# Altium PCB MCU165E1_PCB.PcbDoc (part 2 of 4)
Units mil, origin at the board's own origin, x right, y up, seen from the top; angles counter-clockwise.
Board outline 2658.83 x 2179.35 mil, 6 copper layers (Top Signal Layer, GND1, Mid Layer, PWR, GND2, Bottom Signal Layer), stack 60.4 mil thick; 226 components, 197 nets, 947 pads, 562 vias.
Unrouted connection lines stored in the file: 81.
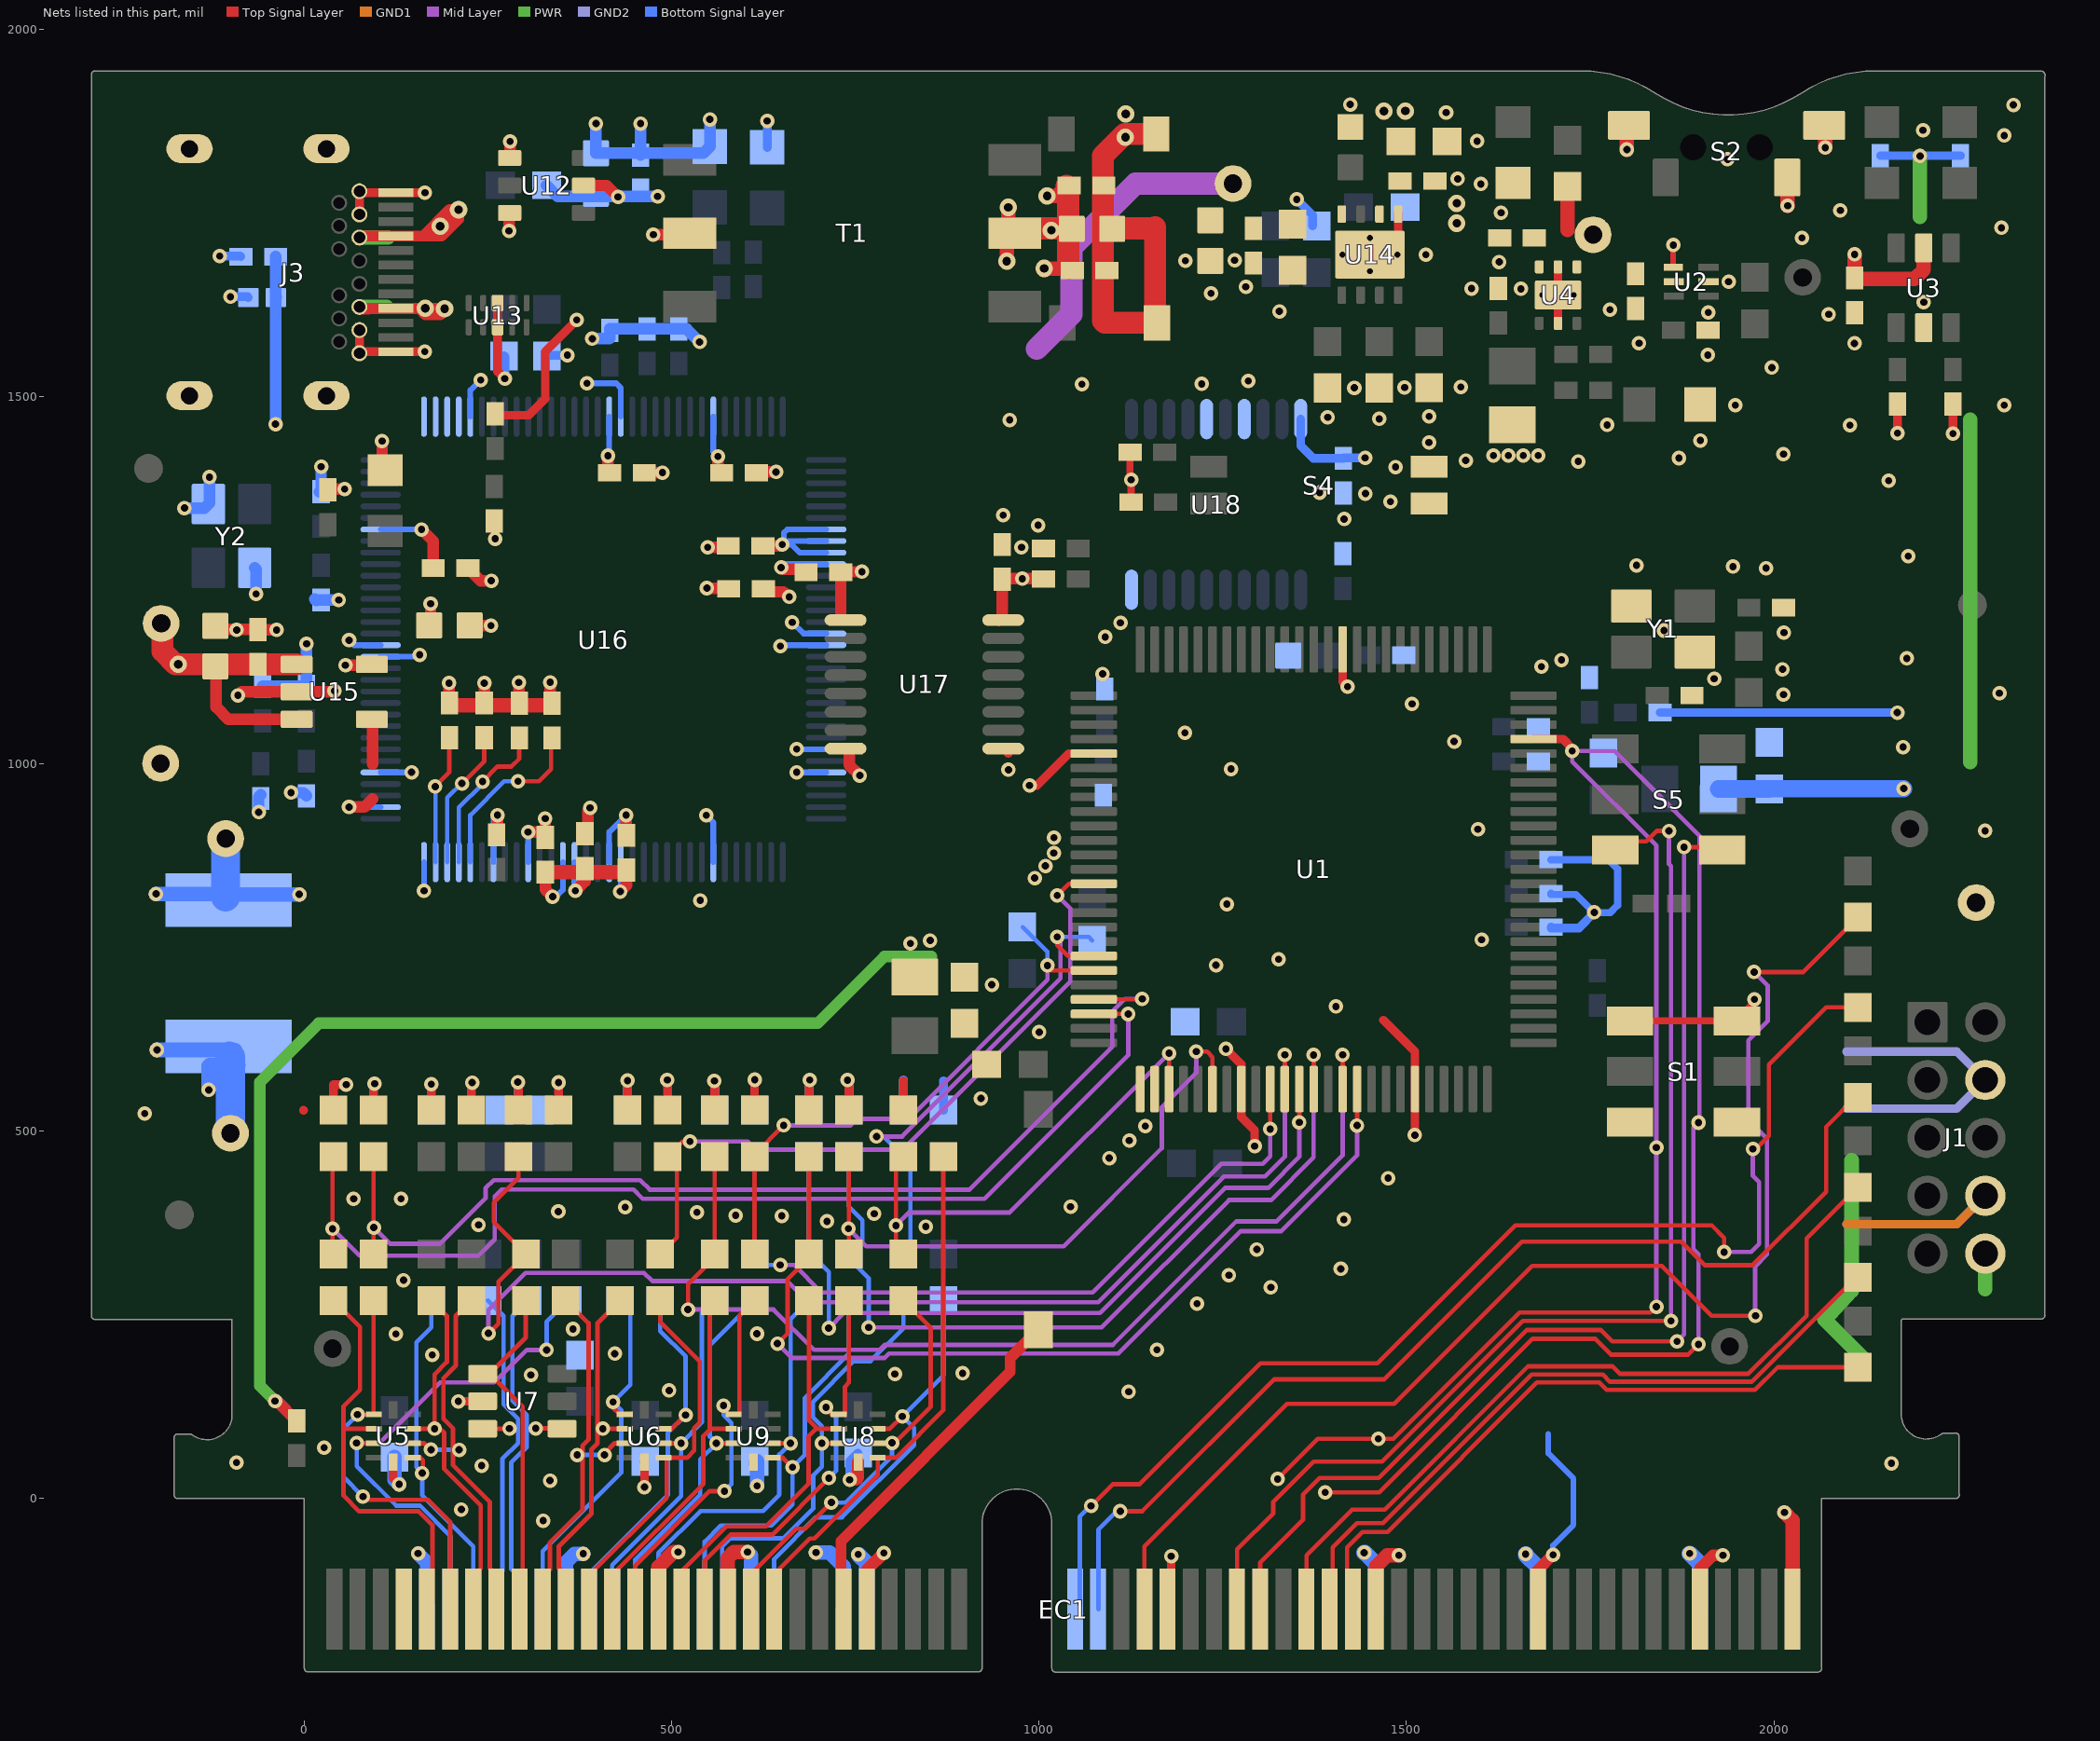
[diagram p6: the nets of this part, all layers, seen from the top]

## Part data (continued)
R13 R18: library part CMP-0026890-5, "RES, 2.2 k, 5%, 0.063 W, AEC-Q200 Grade 0, 0402", Manufacturer=Vishay-Dale, Power_W=63mW, Supplier Part Number 1=541-2.2KJCT-ND, TempCo="200 ppm/C", Tolerance_%=5%, Value2=0.063W, Value_Code=2k20, ValueDisplayed=2.2k
R16 R17: library part CMP-0026992-3, "RES, 0, 5%, 0.1 W, AEC-Q200 Grade 0, 0402", Manufacturer=Panasonic, Power_W=100mW, Supplier Part Number 1=P0.0JCT-ND, TempCo="600 ppm/C", Tolerance_%=5%, Value2=0.1W, Value_Code=0000, ValueDisplayed=0
R19 R20: library part CMP-0026979-3, "RES, 820, 5%, 0.063 W, AEC-Q200 Grade 0, 0402", Manufacturer=Vishay-Dale, Power_W=63mW, Supplier Part Number 1=541-820JCT-ND, TempCo="200 ppm/C", Tolerance_%=5%, Value2=0.063W, Value_Code=820R, ValueDisplayed=820
R21 R22: library part CMP-0026863-2, "RES, 1.5 M, 5%, 0.063 W, AEC-Q200 Grade 0, 0402", Manufacturer=Vishay-Dale, Power_W=63mW, Supplier Part Number 1=541-1.5MJCT-ND, TempCo="200 ppm/C", Tolerance_%=5%, Value2=0.063W, Value_Code=1M50, ValueDisplayed=1.5M
R23 R63 R67 R74: library part CMP-0025874-4, "RES, 0, 5%, 0.1 W, AEC-Q200 Grade 0, 0603", Manufacturer=Panasonic, Power_W=100mW, Supplier Part Number 1=P0.0GCT-ND, TempCo="600 ppm/C", Tolerance_%=5%, Value2=0.1W, Value_Code=0000, ValueDisplayed=0
R24: library part CMP-0020442-3, "RES, 0, 5%, 0.125 W, AEC-Q200 Grade 0, 0805", Manufacturer=Vishay-Dale, Power_W=125mW, Supplier Part Number 1=541-0.0ACT-ND, TempCo="200 ppm/C", Tolerance_%=5%, Value2=0.125W, Value_Code=0000, ValueDisplayed=0
R25: library part CMP-0026944-3, "RES, 510, 5%, 0.063 W, AEC-Q200 Grade 0, 0402", Manufacturer=Vishay-Dale, Power_W=63mW, Supplier Part Number 1=541-510JCT-ND, TempCo="200 ppm/C", Tolerance_%=5%, Value2=0.063W, Value_Code=510R, ValueDisplayed=510
R62: library part CMP-0026100-2, "RES, 1.00 M, 1%, 0.063 W, AEC-Q200 Grade 0, 0402", Manufacturer=Vishay-Dale, Power_W=63mW, Supplier Part Number 1=541-1.00MLCT-ND, TempCo="100 ppm/C", Tolerance_%=1%, Value2=0.063W, Value_Code=1M00, ValueDisplayed=1.00M
R64 R65: library part CMP-0025932-5, "RES, 5.1 k, 5%, 0.1 W, 0603", Manufacturer=Yageo, Power_W=100mW, Supplier Part Number 1=311-5.1KGRCT-ND, TempCo="100 ppm/C", Tolerance_%=5%, Value2=0.1W, Value_Code=5k10, ValueDisplayed=5.1k
R66: library part CMP-0025769-4, "RES, 2.2 k, 5%, 0.1 W, AEC-Q200 Grade 0, 0603", Manufacturer=Vishay-Dale, Power_W=100mW, Supplier Part Number 1=541-2.2KGCT-ND, TempCo="200 ppm/C", Tolerance_%=5%, Value2=0.1W, Value_Code=2k20, ValueDisplayed=2.2k
R68 R69: library part CMP-0025701-4, "RES, 10 k, 5%, 0.1 W, AEC-Q200 Grade 0, 0603", Manufacturer=Vishay-Dale, Power_W=100mW, Supplier Part Number 1=541-10KGCT-ND, TempCo="200 ppm/C", Tolerance_%=5%, Value2=0.1W, Value_Code=10k0, ValueDisplayed=10k
R70: library part CMP-0025927-5, "RES, 4.7 k, 5%, 0.1 W, 0603", Manufacturer=Yageo, Power_W=100mW, Supplier Part Number 1=311-4.7KGRCT-ND, TempCo="100 ppm/C", Tolerance_%=5%, Value2=0.1W, Value_Code=4k70, ValueDisplayed=4.7k
R71: library part CMP-0022895-5, "RES, 1.00 k, 1%, 0.1 W, 0603", Manufacturer=Yageo, Power_W=100mW, Supplier Part Number 1=311-1.00KHRCT-ND, TempCo="100 ppm/C", Tolerance_%=1%, Value2=0.1W, Value_Code=1k00, ValueDisplayed=1.00k
R72: library part CMP-0023109-5, "RES, 430, 1%, 0.1 W, 0603", Manufacturer=Yageo, Power_W=100mW, Supplier Part Number 1=311-430HRCT-ND, TempCo="100 ppm/C", Tolerance_%=1%, Value2=0.1W, Value_Code=430R, ValueDisplayed=430
R73: library part CMP-0025894-5, "RES, 1.2 k, 5%, 0.1 W, 0603", Manufacturer=Yageo, Power_W=100mW, Supplier Part Number 1=311-1.2KGRCT-ND, TempCo="100 ppm/C", Tolerance_%=5%, Value2=0.1W, Value_Code=1k20, ValueDisplayed=1.2k
R76: library part CMP-0026962-3, "RES, 680, 5%, 0.063 W, AEC-Q200 Grade 0, 0402", Manufacturer=Vishay-Dale, Power_W=63mW, Supplier Part Number 1=541-680JCT-ND, TempCo="200 ppm/C", Tolerance_%=5%, Value2=0.063W, Value_Code=680R, ValueDisplayed=680
R78 R79 R80 R81: library part CMP-0026852-3, "RES, 1.0 k, 5%, 0.063 W, AEC-Q200 Grade 0, 0402", Manufacturer=Vishay-Dale, Power_W=63mW, Supplier Part Number 1=541-1.0KJCT-ND, TempCo="200 ppm/C", Tolerance_%=5%, Value2=0.063W, Value_Code=1k00, ValueDisplayed=1.0k
R83: library part CMP-0026824-3, "RES, 100, 5%, 0.063 W, AEC-Q200 Grade 0, 0402", Manufacturer=Vishay-Dale, Power_W=63mW, Supplier Part Number 1=541-100JCT-ND, TempCo="200 ppm/C", Tolerance_%=5%, Value2=0.063W, Value_Code=100R, ValueDisplayed=100
R84 R85: library part CMP-0026699-1, "RES, 470, 1%, 0.1 W, AEC-Q200 Grade 0, 0402", Manufacturer=Panasonic, Power_W=100mW, Supplier Part Number 1=P470LCT-ND, TempCo="100 ppm/C", Tolerance_%=1%, Value2=0.1W, Value_Code=470R, ValueDisplayed=470
R88: library part CMP-0026413-2, "RES, 4.87 k, 1%, 0.063 W, AEC-Q200 Grade 0, 0402", Manufacturer=Vishay-Dale, Power_W=63mW, Supplier Part Number 1=541-4.87KLCT-ND, TempCo="100 ppm/C", Tolerance_%=1%, Value2=0.063W, Value_Code=4k87, ValueDisplayed=4.87k
R89: library part CMP-0026946-3, "RES, 51, 5%, 0.063 W, AEC-Q200 Grade 0, 0402", Manufacturer=Vishay-Dale, Power_W=63mW, Supplier Part Number 1=541-51JCT-ND, TempCo="200 ppm/C", Tolerance_%=5%, Value2=0.063W, Value_Code=51R0, ValueDisplayed=51
R92: library part CMP-0023387-3, "RES, 50, 0.1%, 0.125 W, 0603", Manufacturer="Vishay Thin Film", Power_W=125mW, Supplier Part Number 1=FC0603-50BFCT-ND, TempCo="25 ppm/C", Tolerance_%=0.1%, Value2=0.125W, Value_Code=50R0, ValueDisplayed=50
S1: library part CMP-0002233-1, "Switch, Dual SPDT,  2 Pos, 0.1A, 6VDC, SMD", CurrentRating_mA=100A, Manufacturer="Copal Electronics", Supplier Part Number 1=CASD20JCT-ND
S2: library part CMP-0002328-1, "Switch, SPST, 0.05 A, 12 VDC, SMD", CurrentRating_mA=50A, Manufacturer=Diptronics
S3: library part CMP-0002163-2, "Switch, Slide, SPST, Top Slide, SMT", CurrentRating_mA=100A, Manufacturer="Copal Electronics", Supplier Part Number 1=563-1004-1-ND
S4: library part CMP-0002230-1, "Switch, SPST, 2 Pos, 25mA, 24VDC, SMD", CurrentRating_mA=25A, Manufacturer="CTS Electrocomponents", Supplier Part Number 1=CT2182LPST-ND
S5: library part CMP-0002123-2, "SLIDE SWITCH DPDT  .1A, SMT", CurrentRating_mA=100A, Manufacturer="Copal Electronics", Supplier Part Number 1=CAS220JCT-ND
T1: library part CMP-0030623-1, "Transformer, 105uH, TH", Manufacturer="Wurth Elektronik", ValueDisplayed=105uH
TP1 TP2 TP3 TP4 TP5 TP6 TP7 TP8 TP9 TP10 TP11: library part CMP-0078143-3, "TEST POINT.  No entry in BOM.", Manufacturer=N/A
U1: library part CMP-0124912-2, "Real-Time Microcontroller, LQFP100", Frequency_Fixed=160MHz, Manufacturer="Texas Instruments", Max Supply Voltage=3.63V, Min Supply Voltage=1.14V, Operating Temperature Range="-40¡ãC to +150?"
U2: library part CMP-0750051-1, "Overvoltage and Undervoltage Reset IC With Time Delay and Manual Reset, DSE0006A (WSON-6)", Alternate Manufacturer="Texas Instruments"
U3: library part CMP-0051789-2, "Dual Buffer/Driver with Open-Drain Output, DBV0006A, LARGE T&R", F @ Nom Voltage(Max)(Mhz)=150, Generic Part Number=SN74LVC2G07, ICC @ Nom Voltage(Max)(mA)=0.01, Manufacturer="Texas Instruments", Operating Temperature Range(C)="-40 to 125", Rating=Catalog, tpd @ Nom Voltage(Max)(ns)=8.6,4.4,3.7,2.9, Voltage(Nom)(V)=1.8,2.5,3.3,5
U4: library part CMP-0076262-4, "500-mA Low-Noise, Low-IQ LDO, DRV0006A (WSON-6)", Alternate Manufacturer="Texas Instruments", Alternate PartNumber=LP5912-3.3DRVT
U5 U6 U8 U9: library part CMP-0043123-1, "Low-Capacitance + / - 15 kV ESD Protection Array for High-Speed Data Interfaces, 6 Channels, -40 to +85 degC, 10-pin UQFN (RSE), Green (RoHS & no Sb/Br)", Breakdown Voltage(Min)(V)=11, IO Capacitance(Typ)(pF)=1.5, IO Leakage Current(nA)=1, Manufacturer="Texas Instruments"
U7: library part CMP-0066599-1, "Automotive Low-Capacitance 4-Channel +/-15-kV ESD Protection Array for High-Speed Data Interfaces, DBV0006A (SOT-23-6)", Alternate Manufacturer="Texas Instruments"
U12: library part CMP-0076095-1, "Low-Noise 1 A, 420 kHz Transformer Driver, DBV0006A (SOT-23-6)", Alternate Manufacturer="Texas Instruments", Alternate PartNumber=SN6505BDBVT
U13: library part CMP-0073613-3, "4-Channel Ultra-Low-Capacitance IEC ESD Protection Diode, DQA0010A (USON-10)", Alternate Manufacturer="Texas Instruments"
U14: library part CMP-0043361-3, "Dual In / Single Out Autoswitching Power Mux, 2.8 to 5.5 V, -40 to 85 degC, 9-pin SON (DRB), Green (RoHS & no Sb/Br)", IN1 Output Current(Max)(A)=1.25, IN1, IN2 Input Voltage(Max)(V)=5.5, IN1, IN2 Input Voltage(Min)(V)=2.8, Manufacturer="Texas Instruments"
U15: library part CMP-0091939-1, "Linear Voltage Regulator IC Positive Fixed 1 Output 300mA SOT-23-5", Digikey Part Number=296-47851-1-ND, Dropout Voltage=260mV, Manufacturer="Texas Instruments", Max Supply Voltage=5.5V, Min Supply Voltage=2V, Mouser Part Number=595-TLV70333DBVR, Nominal Supply Current=35-370uA, Operating Temperature Range="-40¡ãC to +125?", Output Voltage=3.3V
U16: library part CMP-0077953-1, "MSP432E401YTPDT, PDT0128A (TQFP-128)", Alternate Manufacturer="Texas Instruments", Alternate PartNumber=MSP432E401YTPDTR
U17: library part CMP-0067607-3, "High Speed, Robust EMC, Reinforced Six-Channel Digital Isolator, DBQ0016A (SSOP-16)", Alternate Manufacturer="Texas Instruments", Alternate PartNumber=ISO7762DBQ
U18: library part CMP-0047070-3, "Octal Buffer/Driver With 3-State OUtputs, PW0020A (TSSOP-20)", Alternate Manufacturer="Texas Instruments", Alternate PartNumber=SN74ALVC244PW, F @ Nom Voltage(Max)(Mhz)=100, Generic Part Number=SN74ALVC244, ICC @ Nom Voltage(Max)(mA)=0.024, Operating Temperature Range(C)="-40 to 85", Rating=Catalog, tpd @ Nom Voltage(Max)(ns)=4.4,3.1,2.8, Voltage(Nom)(V)=1.8,2.5,2.7,3.3
Y1: library part CMP-0093781-1, "20 MHz ¡À10ppm Crystal 8pF 50 Ohms 4-SMD, No Lead", Digikey Part Number=1923-830108207209CT-ND, Frequency_Fixed=20MHz, Frequency Stability=20ppm, Frequency Tolerance=10ppm, Load Capacitance=8pF, Manufacturer="Wurth Electronics", Mouser Part Number=710-830108207209, Operating Temperature Range="-40¡ãC to +85?"
Y2: library part CMP-0094478-1, "Crystal 16 MHz ¡À20ppm Crystal 8pF 70 Ohms 4-SMD, No Lead", Digikey Part Number=732-830064296CT-ND, Frequency_Fixed=16MHz, Frequency Stability=20ppm, Load Capacitance=8pF, Manufacturer=Wurth, Mouser Part Number=710-830064296, Operating Temperature Range="-10¡ãC to +70?"
ZZ1: library part CMP-0003616-3
ZZ2: library part CMP-0077236-1
ZZ3: library part CMP-0077237-1
ZZ4 ZZ5: library part CMP-0077238-1

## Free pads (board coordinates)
  oval 62.99x39.37 on Top Paste paste-100 mask+1.97: 0(-156,1500.78) 0(-156,1837) 0(30.22,1500.78) 0(30.22,1837)
  round 21.65 on Top Paste paste-100 mask+1.97: 0(47.54,1574.4) 0(47.54,1605.9) 0(47.54,1637.39) 0(47.54,1700.39) 0(47.54,1731.88) 0(47.54,1763.38) 0(75.1,1558.65) 0(75.1,1590.15) 0(75.1,1621.65) 0(75.1,1653.14) 0(75.1,1684.64) 0(75.1,1716.13) 0(75.1,1747.63) 0(75.1,1779.13)
  round 11.81 on Top Overlay paste-100 mask+1.97: 19(-289.73,-236) 20(2369,-236) 21(2369,1943) 22(-289.73,1943)

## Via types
v1: diameter 19.68, hole 9.84, Top Signal Layer to Bottom Signal Layer, tented both sides, 540 vias
v2: diameter 23.62, hole 11.81, Top Signal Layer to Bottom Signal Layer, tented both sides, 16 vias
v3: diameter 19.68, hole 7.99, Top Signal Layer to Bottom Signal Layer, tented bottom, 4 vias
v4: diameter 19.68, hole 7.87, Top Signal Layer to Bottom Signal Layer, tented bottom, 2 vias

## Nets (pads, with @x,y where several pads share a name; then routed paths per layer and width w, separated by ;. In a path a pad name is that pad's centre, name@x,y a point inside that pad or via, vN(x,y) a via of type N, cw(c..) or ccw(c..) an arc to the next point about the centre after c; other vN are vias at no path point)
3V3: C3.1 C11.1 C22.1 C92.2 C93.1 EC1.119 J1.10 L1.1 L2.1 R1.1 R2.2 R11.2 R12.2 R13.2 R16.1 R18.2 R19.2 R20.2 R21.2 R22.2 R24.2 R90.2 R91.2 S1.1 S1.4 TP10.1 U2.1 U3.5 U17.16 U18.20 | length 4321
  Top Signal Layer w7.87: U2.1@1863.02,1675.68 1863.02,1705.74 v1(1863.12,1705.84)
  Top Signal Layer w9.84: R90.2@1123.82,1423.67 1123.82,1387.6 1125.13,1386.29 R91.2@1125.13,1355.99 ; S1.1@1804.02,650 S1.4@1949.68,650
  Top Signal Layer w11.81: S1.4@1949.68,650 1973.67,673.99 v1(1973.67,679.22) ; v1(2168.19,1449.78) R21.2@2168.19,1489.38 ; v1(2243.62,1449.36) R22.2@2243.61,1489.38
  Top Signal Layer w15.75: v1(-39.81,132.69) -37.39,132.69 R1.1@-10.38,105.68 ; U17.16@945.27,1195.03 950,1199.76 C93.1@950,1251 950.8,1251.8 v1(977.1,1251.8) 1005.51,1251.8 R18.2@1006.04,1251.27
  Top Signal Layer w19.68: v1(2014.44,-19.03) 2025.31,-29.9 EC1.119@2025.31,-150.67 ; v1@2109.8,1693.16 C3.1@2109.8,1661.04 2110.99,1659.85 2191.49,1659.85 2204,1672.36 U3.5@2204,1701.85
  PWR w15.75: v1(-39.81,132.69) -60.3,153.18 -60.3,566.7 19.72,646.72 698.72,646.72 789.43,737.43 853.49,737.43
  PWR w19.68: 2199,1744.19 v1(2199,1827) ; 2267,1002.14 2267,1468.13 ; 2287.74,284.67 J1.10@2287.74,333.26
  PWR w20: 2105.72,460.43 2105.72,282.43 2069,243.49 2120.52,191.97
  Bottom Signal Layer w9.84: R13.2@1696.62,823.47 1696.62,822.11 1730.57,822.11 1755.54,797.14 1777.24,797.14 1787.29,807.19 1787.29,856.8 1774.72,869.37 R11.2@1696.62,869.37
  Bottom Signal Layer w11.81: U18.20@1356.06,1469.06 1356.06,1432.85 1373.35,1415.56 C92.2@1414.06,1415.56 1414.81,1416.31 v1(1443.74,1416.31) ; R12.2@1696.62,777.57 1696.62,776.4 1734.8,776.4 v1@1755.54,797.14 ; R16.1@1845.16,1069.72 2167.88,1069.72 v1(2168.02,1069.58) ; R19.2@2145,1827.66 R20.2@2253.99,1827.66
  Bottom Signal Layer w15.75: v1(-39.81,132.69) -37.39,132.69 R2.2@-10.38,105.68
  Bottom Signal Layer w23.62: L2.1@1924.95,965.68 1993.85,965.68 C22.1@1994.08,965.91 2176.51,965.91 v1(2176.74,966.14)
  other v1: 824.81,755.26 851.8,759.41 1755.54,797.72 1125.27,1386.43 1618.44,1419.41 1638.75,1419.41 1659.06,1419.41 1679.37,1419.41 2109.85,1693.21
5V0: C4.1 C7.1 R67.1 R71.2 TP11.1 U2.2 U4.4 U4.6 | length 59.1
  Top Signal Layer w19.68: 1719,1726.37 R71.2@1719,1785.5
  other v2: 1568.5,1735.66 1568.5,1762.8
DEBUG_ID4: R78.1 U16.63 | length 165.1
  Top Signal Layer w5.98: v1(178.23,968.86) 178.23,969.3 197.48,988.55 R78.1@197.48,1022.21
  Bottom Signal Layer w5.98: U16.63@178.78,866.06 v1@178.78,969.86
DEBUG_ID5: R79.1 U16.62 | length 188.4
  Top Signal Layer w5.98: v1(214.57,973.21) 244.95,1003.59 R79.1@244.95,1032.38
  Bottom Signal Layer w5.98: U16.62@194.53,866.06 194.53,953.61 v1@215.13,974.21
DEBUG_ID6: R80.1 U16.61 | length 216.8
  Top Signal Layer w5.98: v1(242.57,975.71) 263.06,996.19 282.19,996.19 292.49,1006.49 292.49,1031.1 R80.1@291.21,1032.38
  Bottom Signal Layer w5.98: U16.61@210.28,866.06 210.28,940.36 243.13,973.21 v1@243.13,980.21
DEBUG_ID7: R81.1 U16.60 | length 239.7
  Top Signal Layer w5.98: v1(290.83,976.21) 319.43,976.21 335.86,992.64 335.86,1031.94 R81.1@335.42,1032.38
  Bottom Signal Layer w5.98: U16.60@226.03,866.06 226.03,930.1 272.13,976.21 v1(290.83,976.21)
EMU_3V3: C73.2 C77.1 C78.1 C79.1 C80.1 C81.1 C82.1 C83.1 C84.1 C91.1 R76.1 R78.2 R79.2 R80.2 R81.2 R86.2 R89.2 TP8.1 U15.5 U16.7 U16.8 U16.9 U16.16 U16.26 U16.28 U16.39 U16.47 U16.51 U16.52 U16.69 U16.79 U16.90 U16.101 U16.113 U16.122 U17.1 | length 1821.3
  Top Signal Layer w15.75: R76.1@32,1372.62 33.11,1373.73 v1(55.06,1373.73) ; v1(56,1133.97) 90.75,1133.97 U15.5@91.98,1135.21 ; v1(159.59,1318.81) 175.51,1302.9 C79.1@175.51,1266.21 ; C73.2@169.92,1188.21 172,1190.29 v1(172,1217.77) ; v1(197.16,1109.76) 197.16,1081.81 196.32,1080.97 R78.2@197.67,1079.62 ; R79.2@244.95,1079.62 245.12,1079.79 245,1079.91 v1(245,1109.76) ; R80.2@291.21,1079.62 292.05,1080.47 290.89,1081.63 292,1082.75 v1(292,1110.44) ; C82.1@328,852.38 328.24,852.13 328.24,828.76 v1(338,819) ; v1(334.71,1110.82) 334.71,1081.11 334.32,1080.72 R81.2@335.42,1079.62 ; v1(369,827) 382,840 382,852.38 C80.1@382,862.16 ; v1(413.17,1419.13) 413.17,1398.54 C77.1@415.51,1396.21 ; v1(430,826) 438.43,834.43 C78.1@438.43,855.21 ; v1(563.13,1418.21) 563.13,1401.21 C84.1@568.13,1396.21 ; C81.1@620.13,1237.85 624.07,1233.91 652.02,1233.91 658.93,1227 v1(660,1227) ; C83.1@624.13,1296.21 648.44,1296.21 v1(650.44,1298.21) ; U17.1@730.13,1199 C91.1@730.13,1260.54 730.8,1261.21 v1(759.13,1261.21)
  Top Signal Layer w19.68: R78.2@197.67,1079.62 244.95,1079.62 291.21,1079.62 333.22,1079.62 R81.2@334.32,1080.72 ; C82.1@328,852.38 382,852.38 435.6,852.38 C78.1@438.43,855.21
  Bottom Signal Layer w7.87: U16.69@103.98,988.1 145.88,988.1 v1(146.13,988.36) ; U16.79@103.98,1145.58 154.58,1145.58 v1(157.21,1148.21) ; U16.90@103.98,1318.81 v1(159.59,1318.81) v1@161.59,1318.81 ; U16.101@226.03,1472.36 226.03,1508.1 v1(240.13,1522.21) ; v1(338,819) 340.26,821.26 344.82,821.26 352.01,828.45 U16.52@352.01,866.06 ; U16.51@367.76,866.06 367.76,828.24 v1(369,827) ; v1(413.17,1419.13) 415,1420.96 U16.113@415,1472.36 ; v1(430,826) 430.75,826.75 U16.47@430.75,866.06 ; v1(547,929.85) 556.74,920.12 U16.39@556.74,866.06 ; U16.122@556.74,1472.36 556.74,1424.6 v1(563.13,1418.21) ; v1(650.44,1298.21) 652.7,1300.47 652.7,1314.2 657.32,1318.81 U16.7@710.28,1318.81 ; v1(664.13,1192.45) 679.5,1177.08 U16.16@710.28,1177.08 ; v1(670.13,988.32) 670.34,988.1 U16.28@710.28,988.1 ; v1(670.13,1019.81) 670.34,1019.6 U16.26@710.28,1019.6 ; U16.9@710.28,1287.32 674.25,1287.32 663.36,1298.21 ; U16.8@710.28,1303.06 675,1303.06 v1@658.5,1303.06 ; v1@658.5,1303.06 663.36,1298.21 ; v1@658.5,1303.06 653.64,1298.21 663.36,1298.21
  Bottom Signal Layer w15.75: R89.2@-56.87,1105.45 R86.2@3.13,1105.45 v1@3.13,1162.13
  other v1: 3.13,1163.34
EMU_5V0: C62.1 C63.1 C64.1 C72.2 C74.1 J3.A4 J3.A9 J3.B4 J3.B9 R62.2 R63.2 R83.1 T1.5 TP7.1 U12.2 U15.1 U15.3 | length 1653.7
  Top Signal Layer w11.81: R83.1@265,1474.28 305.41,1474.28 328,1496.87 328,1561 v1@371,1604
  Top Signal Layer w15: J3.B4@75.1,1621.65 77.7,1619.05 87.31,1619.05 87.47,1618.89 88.26,1619.68 J3.A9@124.71,1619.68 v2@156.25,1619.68 ; J3.B9@75.1,1716.13 77.07,1718.1 J3.A4@124.71,1718.1 162.05,1718.1 ; v2(191,1619.05) v2@193.27,1619.05 ; v2@156.25,1619.68 164.65,1611.28 185.5,1611.28 v2@193.27,1619.05 ; v2@156.25,1619.68 v2(164.61,1619.68) 193.9,1619.68 v2@193.27,1619.05 ; 162.05,1718.1 197.94,1754 v2(210,1754) ; 162.05,1718.1 172.39,1718.1 ; 172.39,1718.1 186.94,1718.1 210,1741.16 v2(210,1754) ; 172.39,1718.1 185,1730.72 v2(185,1731.58) 187.58,1731.58 v2(210,1754)
  Top Signal Layer w15.75: v2(-171.38,1135.38) v2@-171.21,1135.21 ; C72.2@-127,1129 -120,1122 -120,1077.03 -103.37,1060.4 U15.3@-10.38,1060.4 ; U12.2@380,1787 411.4,1787 v1(427,1771.4) ; v1(475,1720) 515.28,1720 T1.5@518,1717.28
  Top Signal Layer w30: TP7.1@-192.87,1191.21 -193,1191.08 -193,1153 -175.38,1135.38 v2(-171.38,1135.38) ; v2@-171.21,1135.21 U15.1@-10.38,1135.21
  PWR w19.68: J3.B4@75.1,1621.65 112.35,1621.65 ; J3.B9@75.1,1716.13 113.87,1716.13
  Bottom Signal Layer w15.75: v1(-39.06,1462.14) -38.77,1462.43 -38.77,1634.53 -39,1634.76 -38.74,1635.02 R62.2@-38.74,1689.74 ; C62.1@-37.98,1635 C62.1@-38.48,1634.5 -38.74,1634.76 R62.2@-38.74,1689.74 ; R63.2@329.8,1787 344.8,1772 v1(481,1772) ; R62.2@-38.74,1689.74 R62.2@-39,1690 R62.2@-38.74,1689.74
  other v1: 370.74,1604
EMU_GND: C62.2 C63.2 C64.2 C72.1 C73.1 C74.2 C76.2 C77.2 C78.2 C79.2 C80.2 C81.2 C82.2 C83.2 C84.2 C85.2 C86.2 C87.2 C88.2 C89.2 C90.2 C91.2 C94.2 D4.2 D5.2 D7.1 J3.A1 J3.A12 J3.B1 J3.B12 J3.M1 J3.M2 J3.S1 J3.S2 J3.S3 J3.S4 R62.1 R64.1 R65.1 R87.1 R88.1 TP9.1 U12.4 U12.6 U13.3@263.14,1594.13 U13.8@263.14,1627 U15.2 U15.4 U16.10 U16.17 U16.48 U16.55 U16.58 U16.64 U16.66 U16.80 U16.114 U17.8 Y2.2 Y2.4 | length 2812.5
  Top Signal Layer w7.87: C82.2@320.62,907 C82.2@328,899.62
  Top Signal Layer w12: J3.M1@75.1,1590.15 J3.B1@75.1,1558.65 77.07,1560.62 J3.A12@124.71,1560.62 163.89,1560.62 v1(164,1560.73) ; J3.M2@75.1,1747.63 J3.B12@75.1,1779.13 77.07,1777.16 J3.A1@124.71,1777.16 164.17,1777.16 v1(164.33,1777) ; C76.2@258.79,1330.21 259.76,1329.24 v1(259.76,1306.21) ; U13.8@263.14,1627 U13.3@263.14,1594.13 263.14,1533.86 v1(273,1524)
  Top Signal Layer w15.75: C72.1@-119,1187.56 -114.06,1182.62 C74.2@-63,1182.62 -61,1182.62 -61.62,1182 v1(-37.62,1182) ; v1(-90.25,1093) -85.44,1097.8 U15.2@-10.38,1097.8 v1@41.2,1097.8 ; v1(61,941) 81.92,941 93.13,952.21 ; U15.4@91.98,1060.4 93.13,1059.25 93.13,999.45 ; v1(106,1439) 106,1403.34 D7.1@110,1399.34 ; C79.2@222.75,1266.21 239.96,1249 v1(254.58,1249) ; C73.1@225.04,1188.21 225.24,1188 v1(254,1188) ; R88.1@261.66,903.21 263,904.54 v1(263,930.1) ; v1(278.61,1725) 278.61,1748.6 U12.6@279.61,1749.6 ; U12.4@279.61,1824.4 280,1824.8 v1(280,1847) ; v1(304.6,907) C82.2@320.62,907 ; C82.2@328,899.62 v1(328,925.21) ; C80.2@382,899.84 385.94,903.78 385.94,935.87 389,938.93 v1(389,940) ; v1(438,930) 438,902.88 C78.2@438.43,902.45 ; C77.2@462.75,1396.21 v1(487.4,1396.21) ; v1(548,1239) 548.58,1238.42 580.27,1238.42 C81.2@580.85,1239 ; v1(549.13,1294.37) 575.05,1294.37 C83.2@576.89,1296.21 ; C84.2@615.37,1396.21 616.17,1397 v1(642,1397) ; v1(649,1267) 650.07,1267 652.59,1264.47 678.95,1264.47 C91.2@682.89,1260.54 ; U17.8@736.72,1020.5 741.77,1020.5 741.77,998.23 v1(756,984)
  Bottom Signal Layer w7.87: v1(61,941) 61.14,940.86 U16.66@103.98,940.86 ; v1(61,1168) 67.67,1161.33 U16.80@103.98,1161.33 ; v1(163.04,827) U16.64@163.04,866.06 ; U16.58@257.52,866.06 257.52,924.63 v1(263,930.1) ; v1(304.6,907) 304.77,906.83 U16.55@304.77,866.06 ; v1(384.77,1517.69) 424.69,1517.69 430.75,1511.63 U16.114@430.75,1472.36 ; U16.48@415,866.06 415,907 v1(438,930) ; v1@647,1161.33 U16.17@710.28,1161.33 ; v1(649,1267) 652.2,1267 656.76,1271.57 U16.10@710.28,1271.57
  Bottom Signal Layer w12: v1(-115,1691) -87.24,1691 R62.1@-86.24,1690 ; v1(-100.4,1635.43) -77.09,1635.43 C62.2@-76.16,1634.5 ; R65.1@272,1555.01 273,1554.01 v1(273,1524) ; R64.1@330,1555 331,1556 v1(358.29,1556) ; D4.2@630,1838.88 v1(630,1874.81)
  Bottom Signal Layer w15.75: v1(-163,1348) -135.8,1348 Y2.2@-130.5,1353.31 -129,1354.8 v1(-129,1390) ; Y2.4@-67.5,1266.69 -65.68,1264.87 v1(-65.68,1231) ; v1(-62,934) -62,954.68 C90.2@-59.16,957.52 ; v1(-18,960.61) -1.27,960.61 R87.1@3.13,956.21 ; C88.2@14.13,1223.96 16.09,1222 16.98,1222.89 v1(47,1222.89) ; C89.2@20.94,1370 23,1372.06 v1(23,1404.34) ; v1(392,1578.39) 415.23,1578.39 416.04,1579.2 416.04,1591.74 C85.2@466.77,1591.74 C87.2@509.77,1591.74 520.26,1591.74 v1(538,1574) ; v1(397,1871.21) C63.2@397,1830.86 C64.2@457.69,1830.86 ; C64.2@457.69,1828.24 C64.2@457.69,1830.86 ; v1(457.69,1871.21) C64.2@457.69,1830.86 ; v1(552,1877) D5.2@552,1839.8 543.06,1830.86 C64.2@457.69,1830.86
  Bottom Signal Layer w19.68: v1(-201.61,822.8) C94.2@-112.82,822.8 ; C94.2@-106.87,818.33 C94.2@-103.15,814.61 -95.55,822.2 v1(-6.76,822.2)
  Bottom Signal Layer w39.37: C94.2@-106.87,818.33 TP9.1@-106.87,898.05
  other v1: 539,814 41.2,1099.02 648,1159.94 -92,1182
GND: C1.2 C2.2 C3.2 C4.2 C5.2 C6.1 C7.2 C10.2 C11.2 C12.2 C13.2 C14.2 C15.2 C19.2 C20.2 C21.2 C22.2 C23.2 C24.2 C25.2 C26.1 C27.2 C28.2 C29.2 C30.2 C31.2 C32.2 C33.2 C34.2 C35.2 C36.2 C37.2 C38.2 C39.2 C40.2 C41.2 C42.2 C43.2 C44.2 C45.2 C46.2 C47.2 C48.2 C49.2 C51.2 C52.2 C57.2 C65.2 C66.1 C67.2 C68.1 C69.2 C70.1 C71.2 C92.1 C93.2 C94.1 C95.2 D3.1 D6.1 EC1.7 EC1.10 EC1.22 EC1.29 EC1.35 EC1.38 EC1.46 EC1.47 EC1.65 EC1.83 EC1.97 EC1.111 J1.4 J1.8 R17.2 R68.1 R69.1 R72.1 R73.1 R74.1 S1.3 S1.6 S2.1 S2.2 S2.3 S4.3 S4.4 T1.2 TP6.1 U1.5 U1.26 U1.27 U1.33 U1.45 U1.72 U1.86 U2.5 U3.2 U4.2 U4.5 U4.7@1706.28,1637.76 U5.5 U6.5 U7.2 U8.5 U9.5 U14.5 U14.9@1450.39,1692.88 U17.9 U18.10 U18.15 U18.17 Y1.2 Y1.4 | length 7481.6
  Top Signal Layer w6: v1(1324.69,26.48) 1379.44,81.23 1482.27,81.23 1654.05,253.02 1832.25,253.02 v1(1840.11,260.88) ; v1@1327.14,23.49 v1@1327.14,24.03 ; v1(1389.32,8.3) 1462.99,8.3 1671.95,217.26 1756.84,217.26 1778.3,195.8 1883.47,195.8 v1(1897.4,209.73)
  Top Signal Layer w11.81: -1.1,528.16 -0.77,528.49 ; C29.2@39.81,528.49 39.81,563.32 v1(57.17,563.32) ; C30.2@94.27,528.49 v1@94.27,564.47 ; U5.5@121,49.57 121,27.38 v1(129.17,19.21) ; C32.2@173.03,528.49 v1@173.03,563.99 ; v1(209.81,132.15) 228.27,132.15 228.36,132.24 U7.2@242.76,132.24 ; C31.2@227.5,528.49 v1@227.5,565.92 ; C33.2@291.49,528.49 v1@291.49,566.66 ; C49.2@345.96,528.49 v1(345.96,566.07) ; C46.2@439.95,528.49 v1(439.99,568.75) ; U6.5@462.75,49.57 462.99,49.33 v1(462.99,15.46) ; C35.2@494.42,528.49 v1@494.42,569.5 ; v1(558.16,568.29) 558.42,568.29 C39.2@558.42,528.49 ; C40.2@612.88,528.49 v1@612.88,569.88 ; C44.2@686.88,528.49 686.88,569.41 v1(687.87,569.41) ; C36.2@741.34,528.49 v1@741.34,569.26 ; C41.2@815.34,528.49 815.34,568.54 ; U17.9@951.28,1020.5 U17.9@957.99,1013.8 ; v1(987.12,970.34) 997.2,970.34 1040.66,1013.8 U1.5@1074.57,1013.8 ; EC1.65@1174.92,-150.67 1179.86,-145.73 v1(1179.86,-78.64) ; v1(1254.32,611.82) 1275.36,590.78 U1.33@1275.36,557.1 1275.36,519.21 1293.36,501.21 v1(1293.36,479.47) ; U1.86@1413.16,1155.53 1413.16,1111.43 v1(1419.79,1104.8) ; 1468.81,650.94 1511.58,608.17 U1.45@1511.58,557.1 1511.58,494.71 v1(1511.41,494.54) ; U14.9@1488.77,1692.88 U14.5@1488.77,1748 ; U1.72@1673,1033.48 1713.08,1033.48 1725.64,1020.92 v1(1725.64,1017.45) ; U4.2@1706.28,1599.38 U4.7@1706.28,1637.76 U4.5@1706.28,1676.15
  Top Signal Layer w15.75: EC1.97@1678.86,-150.67 1678.86,-97.32 v1(1699.41,-76.77) ; EC1.111@1899.33,-150.67 1899.33,-95.21 1917.27,-77.27 v1(1930.65,-77.27)
  Top Signal Layer w16.54: v1(742.25,25.42) 751.19,25.42 753.82,28.05 U8.5@753.82,49.57 ; EC1.47@765.47,-150.67 765.47,-97.42 v1(788.82,-74.07)
  Top Signal Layer w19.68: EC1.29@482.01,-150.67 482.01,-93.38 502.46,-72.93 v1(508.83,-72.93) ; EC1.35@576.5,-150.67 576.5,-81.04 584.61,-72.93 v1(603.32,-72.93) ; T1.2@954,1717 T1.2@956,1715 ; v2(956,1684) T1.2@956,1715 ; v2(958,1757.12) 958,1717 957,1716 T1.2@956,1715 ; v2(1007,1674.03) 1040.88,1674.03 C65.2@1045.16,1669.76 ; v2(1011,1772.54) 1023.54,1772.54 C67.2@1037.27,1786.27 ; v2(1016.72,1726) 1037.04,1726 C66.1@1039.63,1728.59 ; EC1.83@1458.39,-150.67 1458.39,-92.82 1473.94,-77.27 v1(1489.71,-77.27) ; v1(1800,1835.81) 1800,1863.8 1798.87,1864.92 S2.2@1802.69,1868.74 ; S2.3@2018.24,1797.87 2018.87,1797.24 v1(2018.87,1759.41) ; S2.1@2068.44,1868.74 2069.87,1867.31 v1(2069.87,1838.41)
  Top Signal Layer w30: T1.2@957,1716 969.59,1728.59 C66.1@1039.63,1728.59 ; C67.2@1037.27,1786.27 1039.63,1783.91 C66.1@1039.63,1728.59 ; C65.2@1040.88,1674.03 1039.63,1675.29 C66.1@1039.63,1728.59
  Mid Layer w6: v1(1840.11,260.88) 1840.19,260.88 1840.19,888.39 1725.64,1002.94 v1(1725.64,1017.45) 1783.25,1017.45 1898.61,902.09 1898.61,510.34 v1(1897.43,511.52) 1890.41,504.5 1890.41,339.51 1897.4,332.52 v1(1897.4,209.73)
  Mid Layer w11.81: v1(209.81,132.15) v1@210.83,131.13
  GND1 w11.81: 2098.88,373.16 2248.9,373.16 J1.8@2287.74,412
  GND2 w11.81: 2098.88,373.16 2248.9,373.16 J1.8@2287.74,412 ; 2098.88,530.64 2248.9,530.64 J1.4@2287.74,569.48 2248.9,608.32 2098.88,608.32
  Bottom Signal Layer w7.87: 1692.98,87.98 1692.98,61.36 1727.24,27.1 1727.24,-35.97 1699.41,-63.8 v1(1699.41,-76.77)
  Bottom Signal Layer w11.81: 291.49,528.49 v1@291.49,566.66 ; C47.2@439.95,528.49 v1(439.99,568.75) ; v1(558.16,568.29) 558.42,568.29 C43.2@558.42,528.49 ; C34.2@612.88,528.49 612.88,569.88 v1(613.14,569.88) ; C37.2@686.88,528.49 686.88,569.41 v1(687.87,569.41) ; C38.2@741.34,528.49 v1@741.34,569.26 ; v1(742.25,25.42) 742.25,50.32 C27.2@753.67,61.74 ; C42.2@815.34,528.49 815.34,569.97 ; C52.2@869.81,528.49 869.81,568.66
  Bottom Signal Layer w19.68: v1(-200.43,610.47) C94.1@-111.64,610.47 ; v1(-130,556) -130,588.82 -128.83,589.99 C94.1@-89.67,589.99 ; C94.1@-101.96,602.28 C94.1@-94.37,609.88 ; C24.2@123,56.34 123,25.38 v1(129.17,19.21) ; v1(154.9,-74.92) 167.05,-87.07 EC1.10@167.05,-150.67 ; EC1.22@356.02,-150.67 356.02,-87.07 367.89,-75.2 v1(379.57,-75.2) ; v1(603.32,-72.93) 607.99,-77.6 EC1.38@607.99,-150.67 ; v1(616.28,17.03) 616.28,46.26 614.18,48.35 C28.2@616.33,50.5 ; v1(696.35,-73.71) 715.14,-73.71 733.98,-92.55 EC1.46@733.98,-150.67
  Bottom Signal Layer w39.37: C94.1@-101.96,602.28 -100.4,600.71 TP6.1@-100.4,497
  other v1: 325.29,-30.2 213.82,-15.04 334.44,24.33 241.57,44.58 2160.17,47.77 -92.15,48.7 27.04,69.06 1461.87,81.23 1122,145.3 496.64,146.87 308.37,168.04 803.72,169.32 895.98,170.46 174.11,195.4 422.53,197.06 1160.49,202.39 124.81,223.87 616.04,224.21 365.82,230.56 1214.89,265.01 1315.37,287.39 135.15,297.07 1258.42,303.88 1410.67,312.49 1296.41,338.94 845.99,369.96 237.23,372.31 711.33,377.18 1414.89,379.67 649.87,384.54 587,385.18 775.66,387.64 534.37,389.35 345.77,390.54 436.82,396.55 1042.88,397.04 67.24,407.94 131.75,407.94 1475.1,435.91 1095.58,463.26 1840.21,477.67 1122.84,486.98 1144.68,506.71 -217.04,524 920.93,544.43 95.87,564.47 172.94,563.99 228.58,565.92 290.76,566.66 494.14,569.5 739.44,569.26 1000.25,634.65 1404.1,669.54 935.75,699.19 1240.84,725.75 1325.92,733.84 1602.26,760.4 1255.54,808.85 2287.45,908.59 1597.29,910.73 958.3,991.75 1261.35,992.81 2175.8,1022.68 1564.81,1030.22 1198.48,1041.92 1507.56,1081.24 2013.09,1094.06 2306.9,1096.03 1918.82,1115.6 1086.44,1122.2 2011.77,1128.54 1683.58,1131.99 1710.88,1141.27 2180.99,1143.24 1090.16,1172.46 2013.81,1178.48 1850.48,1181.29 1110.7,1191.82 1989.52,1266.17 1944.5,1268.29 1813.18,1269.96 2182.8,1282.53 976.07,1294.36 998.64,1324.55 1415.17,1332.98 951.08,1338.24 1478.12,1356.79 1444.13,1367.6 1381.71,1369.01 2156.17,1385.06 1485.24,1403.87 1733.9,1411.48 1580.79,1412.62 1870.73,1415.95 2013.05,1421.4 1530.58,1437.09 1899.97,1439.97 2103.57,1460.72 1773.13,1461.12 960.17,1467.85 1463.13,1469.35 1392.84,1471.46 1530.87,1472.74 2313.36,1487.88 1947.66,1487.98 1429.05,1511.65 1497.45,1511.89 1573.91,1512.62 1058.33,1516.56 1221.47,1516.9 1284.77,1520.81 1997.18,1539.06 1910.21,1556.21 1816.47,1572.28 2109.75,1572.06 2074.59,1611.54 1910.74,1614.06 1327.04,1615.63 1776.97,1617.88 2204,1628.03 1233.89,1640.12 1588.54,1646.77 1655.72,1646.33 1281.38,1649.05 1938.45,1655.91 1626.18,1682.9 1199.09,1684.4 1266.14,1685.17 1526.39,1692.85 2038.32,1715.55 2309.65,1729.37 1628.8,1749.93 2090.49,1753.07 1601.13,1789 1569.78,1795.95 1936.94,1822.51 1596.12,1847.33 2313.37,1854.87 2202.96,1862.09 1554.01,1886.11 2325.92,1896.65 1423.4,1897.24
  other v3: 1450.39,1670.24 1412.98,1692.88 1487.79,1692.88 1450.39,1715.52
  other v4: 1684.63,1637.76 1727.94,1637.76
HSEC_5V0: C69.1 C70.2 EC1.48 EC1.84 EC1.98 EC1.112 R68.2 R70.2 TP2.1 U14.8 | length 784.9
  Mid Layer w30: 997,1564.88 1044,1611.88 1044,1702.36 1131.21,1789.57 TP2.1@1264,1789.57
  Bottom Signal Layer w11.81: v1(1350.86,1768.09) 1372.2,1746.75 R70.2@1372.2,1731.99
  Bottom Signal Layer w19.68: EC1.112@1899.33,-150.67 EC1.112@1900.31,-149.69
  Bottom Signal Layer w21.65: v1@754.67,-76.94 765.47,-87.74 EC1.48@765.47,-150.67 ; v1(1442.54,-73.76) 1443.29,-73.76 1458.39,-88.86 EC1.84@1458.39,-150.67 ; v1(1662.2,-75.68) 1662.2,-76.98 1678.86,-93.64 EC1.98@1678.86,-150.67 ; v1(1885.39,-74.92) 1899.33,-88.86 EC1.112@1899.33,-150.67
  other v1: 753.97,-76.24 994.02,844.43 1008.57,860.88 1019.99,878.56 1020.26,899.5
HSEC_A0/B15/C15/DACA_OUT: EC1.9 R26.2 U5.2 | length 586.3
  Top Signal Layer w6: R26.2@39.74,269.51 53.47,255.78 76.02,233.23 76.02,147.97 53.47,125.42 53.47,94.44 ; U5.2@94.43,94.84 53.87,94.84 53.47,94.44 ; EC1.9@167.05,-150.67 174.52,-143.2 174.52,-36.19 155.79,-17.46 74.83,-17.46 53.47,3.9 53.47,94.44
HSEC_A1/B7/D11/DACB_OUT: EC1.11 R27.2 U5.1 | length 560.3
  Top Signal Layer w6: v1(72.54,114.07) 93.97,114.07 U5.1@94.43,114.53 94.21,114.75 R27.2@94.21,269.51 ; v1(79.95,2.65) 79.41,2.65 83.88,-1.82 168.71,-1.82 198.54,-31.65 EC1.11@198.54,-150.67
  Bottom Signal Layer w6: v1(72.54,114.07) 53.47,95 53.47,29.13 v1(79.95,2.65)
HSEC_A3/B9/C7: EC1.39 R29.2 U8.6 | length 729.8
  Top Signal Layer w6: EC1.39@639.49,-150.67 639.49,-102.68 687.8,-54.37 694.41,-54.37 780.39,31.61 U8.6@780.39,55.47 805,55.47 869.74,120.22 R29.2@869.74,465.5
HSEC_A4/B8: EC1.17 R30.2 U7.1 | length 470.4
  Top Signal Layer w6.2: U7.1@242.76,169.65 U7.1@252.1,169.65 ; EC1.17@293.03,-150.67 297.19,-146.51 297.19,124.58 U7.1@252.12,169.65 ; R30.2@301.43,269.51 301.43,218.98 U7.1@252.1,169.65
HSEC_A5: EC1.28 R31.2 U9.3 | length 518.4
  Top Signal Layer w6: v1(560.91,75.16) U9.3@584.49,75.16
  Bottom Signal Layer w6: EC1.28@450.51,-150.67 450.51,-83.3 538.83,5.02 538.83,53.08 v1(560.91,75.16) 551.98,84.09 551.98,208.68 R31.2@612.82,269.51
HSEC_A6/D14/E14: EC1.23 R32.2 U6.6 | length 521.2
  Top Signal Layer w6: EC1.23@387.52,-150.67 387.52,-104.91 493.26,0.84 493.26,55.47 521.06,55.47 530.72,65.13 530.72,96.04 538.25,103.57 538.25,186.2 484.35,240.1 R32.2@484.35,269.51
HSEC_A7/B30/C3/D12/E30: EC1.33 R33.2 U8.1 | length 580.5
  Top Signal Layer w6: EC1.33@545,-150.67 545,-84.61 580.43,-49.18 637.07,-49.18 v1(713.86,27.61) ; v1(710.15,124.11) 707.82,124.11 717.4,114.53 U8.1@727.25,114.53 733.41,114.53 735.95,117.07 735.95,152.39 741.28,157.72 R33.2@741.28,269.51
  Mid Layer w6: v1@707.36,124.11 v1(710.15,124.11)
  Bottom Signal Layer w6: v1(710.15,124.11) 723.68,110.58 723.68,37.43 v1(713.86,27.61)
HSEC_A8: EC1.30 R34.2 U9.7 | length 583
  Top Signal Layer w6: U9.7@633.7,75.16 U9.7@637.64,75.16 661.67,75.16 v1(661.76,75.07)
  Bottom Signal Layer w6: EC1.30@482.01,-150.67 482.01,-74.26 539.31,-16.96 624.47,-16.96 646.54,5.11 646.54,59.85 v1(661.76,75.07) 661.77,244.47 R34.2@686.81,269.51
HSEC_A9: EC1.34 R35.2 U9.6 | length 573.9
  Top Signal Layer w6: U9.6@637.64,55.47 651.42,55.47 v1(664.38,42.51)
  Bottom Signal Layer w6: EC1.34@545,-150.67 545,-58.69 567,-36.69 635.82,-36.69 664.38,-8.13 v1(664.38,42.51) 681.3,59.43 681.3,137.02 741.28,197 R35.2@741.28,269.51
HSEC_A10/B1/C10: EC1.25 R36.2 U9.2 | length 510.4
  Top Signal Layer w6: EC1.25@419.02,-150.67 419.02,-104.24 543.07,19.81 543.07,85.06 551.94,93.93 551.94,94.84 ; R36.2@558.35,269.51 551.94,263.1 551.94,94.84 ; U9.2@584.49,94.84 551.94,94.84
HSEC_A11/B10/C0/PGA2_OUT: EC1.27 R37.2 U9.1 | length 539.2
  Top Signal Layer w6: EC1.27@450.51,-150.67 450.51,-91.18 551.64,9.95 v1(571.82,9.95) ; v1(570.5,126.39) 570.5,122.07 578.04,114.53 U9.1@584.49,114.53 590.49,114.53 592.27,116.31 592.27,248.97 R37.2@612.82,269.51
  Bottom Signal Layer w6: v1(570.5,126.39) 570.5,113.5 581.28,102.72 581.28,19.41 v1(571.82,9.95)
HSEC_A12/C5: EC1.37 R38.2 U8.7 | length 577
  Top Signal Layer w6: EC1.37@607.99,-150.67 607.99,-102.57 669.35,-41.21 681.63,-41.21 v1(717.3,-5.54) ; U8.7@780.39,75.16 802.56,75.16 852.59,125.19 852.59,232.19 R38.2@815.27,269.51
  Bottom Signal Layer w6: v1(717.3,-5.54) 736.52,-5.54 799.94,57.88 v1(799.94,75.65)
HSEC_A14/B14/C4/PGA1_OUT: EC1.36 R39.2 U8.3 | length 614.1
  Top Signal Layer w6: v1(704.4,75.16) U8.3@727.25,75.16
  Bottom Signal Layer w6: EC1.36@576.5,-150.67 568.71,-142.88 568.71,-65.57 580.19,-54.09 652.2,-54.09 692.75,-13.54 692.75,31.73 704.4,43.38 v1(704.4,75.16) 704.4,98.26 692.31,110.35 692.31,131.5 747.64,186.83 770.69,186.83 815.27,231.41 R39.2@815.27,269.51
HSEC_B0/C11: EC1.31 R41.2 U8.2 | length 562.6
  Top Signal Layer w6.2: EC1.31@513.5,-150.67 513.5,-98.95 574.37,-38.08 628.23,-38.08 686.45,20.14 686.45,84.95 697.38,95.88 ; R41.2@686.81,269.51 686.81,106.44 697.38,95.88 ; U8.2@727.25,94.84 698.41,94.84 697.38,95.88
HSEC_B2/C6/E12: EC1.14 R42.2 U5.6 | length 493.9
  Top Signal Layer w6: U5.6@147.57,55.47 158.03,55.47 161.4,52.1 161.4,35.32 v1(160.56,34.48)
  Bottom Signal Layer w6: R42.2@173.1,269.51 173.1,232.72 152.66,212.28 152.66,42.38 v1(160.56,34.48) 160.56,4.22 230.04,-65.26 EC1.14@230.04,-150.67
HSEC_B4/C8: EC1.20 R40.2 U6.1 | length 511.6
  Top Signal Layer w6: v1(420.43,131.26) 420.43,123.3 429.2,114.53 U6.1@436.18,114.53
  Bottom Signal Layer w6: EC1.20@324.53,-150.67 324.53,-71.84 431.31,34.94 431.31,120.38 v1(420.43,131.26) 443.67,154.5 443.67,255.73 R40.2@429.89,269.51
HSEC_B5/D15/E15/PGA3_OUT: EC1.26 R44.2 U6.7 | length 501.5
  Top Signal Layer w6: U6.7@489.33,75.16 v1@512.84,75.16
  Bottom Signal Layer w6: EC1.26@419.02,-150.67 419.02,-90.55 512.87,3.3 v1(512.87,75.13) 540.98,103.24 540.98,252.14 R44.2@558.35,269.51
HSEC_B11/D16/E16: EC1.24 R45.2 U6.8 | length 522.3
  Top Signal Layer w6: U6.8@493.26,94.84 499.97,94.84 518.61,113.48 v1(518.94,113.48)
  Bottom Signal Layer w6: EC1.24@387.52,-150.67 387.52,-102.53 494.7,4.65 494.7,89.24 v1(518.94,113.48) 518.94,193.19 484.35,227.78 R45.2@484.35,269.51
HSEC_B12/C2: EC1.12 R46.2 U5.3 | length 711.5
  Top Signal Layer w6: v1(71.31,75.38) 94.2,75.38 U5.3@94.43,75.16
  Mid Layer w6: v1(71.31,75.38) 102.35,75.38 184.75,157.78 258.64,157.78 302.99,202.13 v1(329.88,202.13)
  Bottom Signal Layer w6: v1(71.31,75.38) 71.31,43.96 125.1,-9.83 157.58,-9.83 198.54,-50.79 EC1.12@198.54,-150.67 ; v1(329.88,202.13) 329.88,240.49 R46.2@358.9,269.51
HSEC_C14: EC1.40 R49.2 U8.8 | length 590.2
  Top Signal Layer w6: U8.8@780.39,94.84 797.01,94.84 v1(813.9,111.73)
  Bottom Signal Layer w6: EC1.40@639.49,-150.67 639.49,-82.36 696.18,-25.67 731.95,-25.67 829.87,72.25 829.87,95.76 v1(813.9,111.73) 869.74,167.57 R49.2@869.74,269.51
HSEC_GPIO11: EC1.63 R4.1 | length 1779.1
  Top Signal Layer w6: EC1.63@1143.42,-150.67 1143.42,-65.33 1337.67,128.92 1483.29,128.92 1670.93,316.56 1847.61,316.56 1915.49,248.68 v1(1975.05,248.68) ; v1(1973.1,716.49) 2039.91,716.49 R4.1@2114.35,790.93
  Mid Layer w6: v1(1973.1,716.49) 1991.51,698.08 1991.51,649.72 1965.26,623.47 1965.26,515.07 1990.76,489.57 1990.76,332.1 1974.59,315.93 1974.59,249.14 v1(1975.05,248.68)
HSEC_GPIO12: EC1.58 R3.1 | length 1643.9
  Top Signal Layer w6: v1(1070.85,-10.2) 1100.39,19.34 1136.57,19.34 1301.15,183.92 1460.51,183.92 1648.15,371.56 1915.52,371.56 1932.46,354.62 v1(1932.46,335.36) ; v1(1971.43,475.57) 1975.55,475.57 1993.32,493.34 1993.32,590.48 2071.3,668.46 R3.1@2114.35,668.46
  Mid Layer w6: v1(1932.46,335.36) 1968.89,335.36 1979.76,346.23 1979.76,430.47 1971.43,438.8 v1(1971.43,475.57)
  Bottom Signal Layer w6: EC1.58@1055.43,-144.18 1055.43,-24.8 v1@1065.44,-14.79
HSEC_GPIO13: EC1.60 R5.1 | length 1462.8
  Top Signal Layer w6: v1(1110.6,-17.44) 1140.34,-17.44 1319.7,161.92 1469.62,161.92 1657.26,349.56 1873.91,349.56 1905.95,317.52 1971.33,317.52 2071.1,417.29 2071.1,505.81 2111.27,545.98 R5.1@2114.35,545.98
  Bottom Signal Layer w6: EC1.60@1080.72,-151.11 1080.72,-42.49 v1@1108.04,-15.17
HSEC_GPIO18: EC1.71 S5.3 | length 1556.6
  Top Signal Layer w6: EC1.71@1269.41,-150.67 1269.41,-69.42 1318.76,-20.07 1318.76,-4.7 1373.39,49.94 1466.53,49.94 1658.31,241.72 v1(1859.93,241.72) ; S5.3@1784.17,894.19 1826.18,894.19 1840.48,908.49 v1(1857.28,908.49)
  Mid Layer w6: v1(1857.28,908.49) 1857.28,863.09 1859.93,860.44 v1(1859.93,241.72)
HSEC_GPIO19: EC1.73 S5.6 | length 1521.5
  Top Signal Layer w6: EC1.73@1300.9,-150.67 1300.9,-87.59 1359.22,-29.27 1359.22,5.25 1381.85,27.88 1462.49,27.88 1663.92,229.31 1764.33,229.31 1780,213.64 v1(1868.38,213.64) ; v1(1877.86,886.45) 1905.74,886.45 1906.97,885.22 1915.94,894.19 S5.6@1929.83,894.19
  Mid Layer w6: v1(1868.38,213.64) 1877.86,223.12 v1(1877.86,886.45)
HSEC_GPIO25: EC1.77 R6.1 | length 1101
  Top Signal Layer w6: EC1.77@1363.9,-150.67 1363.9,-77.2 1426.02,-15.08 1470.72,-15.08 1665.63,179.82 1780.06,179.82 1790.1,169.78 1965.35,169.78 2044.47,248.9 2044.47,353.62 R6.1@2114.35,423.5
HSEC_GPIO26: EC1.79 R7.1 | length 961
  Top Signal Layer w6: EC1.79@1395.39,-150.67 1399.6,-146.46 1399.6,-66.82 1432.84,-33.58 1468.1,-33.58 1670.5,168.82 1767.21,168.82 1777.25,158.78 1969.9,158.78 2112.15,301.03 R7.1@2114.35,301.03
HSEC_GPIO27: EC1.81 R8.1 | length 892.3
  Top Signal Layer w6: EC1.81@1426.89,-150.67 1419.16,-142.94 1419.16,-66.72 1440.31,-45.57 1474.12,-45.57 1677.51,157.82 1762.65,157.82 1772.69,147.78 1974.46,147.78 2005.23,178.55 R8.1@2114.35,178.55
HSEC_PGA1_IN_N: EC1.13 R94.2 U5.8 | length 496.1
  Top Signal Layer w6.1: U5.8@147.57,94.84 v1(177.43,94.85) ; R94.2@172.97,269.51 194.15,248.33 194.15,185.7 177.29,168.84 177.29,103.18 182.64,97.83 182.64,97.11 190.52,89.23 190.52,40.24 194.15,36.61 240.28,-9.52 240.28,-95.22 230.04,-105.46 EC1.13@230.04,-150.67
HSEC_PGA1_IN_P: EC1.15 R28.2 U5.7 | length 533.2
  Top Signal Layer w6.1: U5.7@147.57,75.16 162.92,75.16 171.77,66.31 v1(172.51,66.31) ; R28.2@227.43,269.51 206.25,248.33 206.25,180.69 189.39,163.83 189.39,108.19 202.62,94.96 202.62,45.25 252.38,-4.51 252.38,-94.79 261.53,-103.94 EC1.15@261.53,-150.67
  Mid Layer w6.1: v1(172.51,66.31) v1@172.88,65.94
  Bottom Signal Layer w6.1: v1(172.51,66.31) 210.63,66.31 v1(210.74,66.2)
HSEC_PGA2_IN_N: EC1.19 R95.2 U6.3 | length 531.3
  Top Signal Layer w6.2: EC1.19@324.53,-150.67 324.53,-106.22 334.17,-96.58 334.17,-60.05 378.57,-15.66 378.57,71.64 386.79,79.86 386.79,238.61 R95.2@355.89,269.51 ; v1(408.71,59.15) 408.71,61.49 422.38,75.16 U6.3@436.18,75.16
  Bottom Signal Layer w6.2: v1(371.6,59.15) v1(408.71,59.15)
HSEC_PGA2_IN_P: EC1.21 R43.2 U6.2 | length 488.7
  Top Signal Layer w6.2: EC1.21@356.02,-150.67 356.02,-104.5 346.37,-94.85 346.37,-65.11 390.77,-20.71 390.77,66.58 398.99,74.81 398.99,238.61 R43.2@429.89,269.51 ; v1(406.3,94.84) U6.2@436.18,94.84
HSEC_PGA3_IN_N: EC1.16 R96.2 U7.3 | length 496.8
  Top Signal Layer w6.1: U7.3@242.76,94.84 276.99,94.84 v1@277.28,95.13
  Bottom Signal Layer w6.1: R96.2@249.97,269.51 271.15,248.33 271.15,128.06 290.82,108.4 290.82,75.1 269.52,53.8 269.52,-98.47 261.53,-106.46 EC1.16@261.53,-150.67 ; v1@277.28,95.13 v1(279.25,95.13) 290.16,95.13
HSEC_PGA3_IN_P: EC1.18 R48.2 U7.4 | length 486.7
  Top Signal Layer w6.1: v1(315.16,95.32) 350.55,95.32 U7.4@351.02,94.84
  Bottom Signal Layer w6.1: EC1.18@293.03,-150.67 293.03,-107.35 281.62,-95.94 281.62,48.79 302.92,70.09 302.92,113.41 283.25,133.08 283.25,248.33 R48.2@304.44,269.51
HSEC_VREFHIABCDE: EC1.45 S3.2 | length 492.9
  Top Signal Layer w15: EC1.45@733.98,-150.67 730.36,-147.05 730.36,-58.11 960.76,172.29 960.76,191.23 S3.2@999,229.47
ISO_Pout_5V0: C65.1 C66.2 C67.1 C71.1 D9.1 D10.1 R69.2 U14.6 | length 554.5
  Top Signal Layer w30: C66.2@1094.75,1728.59 1148.91,1728.59 ; D10.1@1147.95,1857 1116.49,1857 1086.87,1827.38 1086.87,1788.64 1086.87,1728.59 1086.87,1602.59 1089.46,1600 1158,1600 1158,1730
  other v2: 1117.53,1852.62 1117.84,1884.28 1469.42,1888.15 1498.45,1888.34
ITCK: U16.100
ITDI: U16.98
ITDO: U16.97
ITMS: U16.99
MCU_A0/B15/C15/DACA_OUT: C29.1 R26.1 U1.23 | length 1492.3
  Top Signal Layer w6: R26.1@39.81,332.57 38.58,333.8 v1(38.58,367.04) 38.58,464.28 C29.1@39.81,465.5 ; U1.23@1074.57,659.46 1121.23,659.46 v1(1121.38,659.31)
  Mid Layer w6: v1(38.58,367.04) 75.12,330.5 237.11,330.5 259.36,352.75 259.36,411.27 268.51,420.42 448.04,420.42 460.57,407.89 925.81,407.89 1121.38,603.46 v1(1121.38,659.31)
MCU_A1/B7/D11/DACB_OUT: C30.1 R27.1 U1.22 | length 1439.1
  Top Signal Layer w6: R27.1@94.21,332.5 94.27,332.57 C30.1@94.27,465.5 ; U1.22@1074.57,679.15 1139.71,679.15 v1(1140.45,679.89)
  Mid Layer w6: v1(94.65,368.71) 116.61,346.75 184.89,346.75 246.74,408.6 246.74,422.15 257.9,433.31 457.21,433.31 470.23,420.29 905.33,420.29 1099.46,614.42 1099.46,662.62 1116.73,679.89 v1(1140.45,679.89)
MCU_A4/B8: C33.1 R30.1 U1.36 | length 1736.9
  Top Signal Layer w6: v1(250.67,224.68) 264.14,238.15 264.14,295.22 R30.1@301.43,332.5 257.81,376.12 257.81,402.75 291.49,436.43 C33.1@291.49,455.5 ; C33.1@285.88,449.89 C33.1@291.49,455.5 ; C33.1@291.49,465.5 C33.1@291.49,455.5 ; C33.1@301.49,465.5 C33.1@291.49,455.5 ; U1.36@1334.42,557.1 1334.51,557.2 v1(1334.51,603.92)
  Mid Layer w6: v1(250.67,224.68) 250.67,256.69 300.94,306.96 462.43,306.96 473.41,295.98 656.99,295.98 686.04,266.93 1080.45,266.93 1251.74,438.22 1307.57,438.22 1334.51,465.16 v1(1334.51,603.92)
MCU_A5: C34.1 R31.1 U1.35 | length 1024.4
  Top Signal Layer w6: v1(1314.6,502.76) 1314.73,502.89 U1.35@1314.73,557.1
  Mid Layer w6: v1(647.7,317.68) 666.77,317.68 704.01,280.44 1073.01,280.44 1247.94,455.37 1304.15,455.37 1314.6,465.82 v1(1314.6,502.76)
  Bottom Signal Layer w6: C34.1@612.82,465.44 R31.1@612.82,332.5 627.64,317.68 v1(647.7,317.68)
MCU_A6/D14/E14: C35.1 R32.1 U1.14 | length 984.8
  Top Signal Layer w6: R32.1@484.35,332.5 507.34,355.49 507.34,452.58 C35.1@494.42,465.5 514.62,485.7 v1(524.87,485.7) ; v1(1024.84,820.82) 1040.65,836.63 U1.14@1074.57,836.63
  Mid Layer w6: v1(524.87,485.7) 525.03,485.86 603.36,485.86 614.51,474.71 813.89,474.71 1042.5,703.32 1042.5,803.16 v1(1024.84,820.82)
MCU_A7/B30/C3/D12/E30: C36.1 R33.1 U1.31 | length 844.3
  Top Signal Layer w6: R33.1@741.34,332.57 C36.1@741.34,465.5 ; v1(1214,608.12) 1228.65,608.12 1235.99,600.78 U1.31@1235.99,557.1
  Mid Layer w6: v1(740.6,367.25) 764.67,343.18 1033.65,343.18 1167.11,476.64 1167.11,532.34 1214,579.23 v1(1214,608.12)
MCU_A8: C37.1 R34.1 U1.37 | length 1075.9
  Top Signal Layer w6: v1@1354.1,511.38 v1(1354.1,511.69) U1.37@1354.1,557.1
  Mid Layer w6: v1(713.73,231.81) 734.46,252.54 1082.9,252.54 1252.99,422.63 1311.75,422.63 1354.1,464.98 v1(1354.1,511.69)
  Bottom Signal Layer w6: C37.1@686.81,465.44 R34.1@686.81,332.5 689.59,332.5 713.84,308.25 713.84,231.92 v1(713.73,231.81)
MCU_A9: C38.1 R35.1 U1.38 | length 1146
  Top Signal Layer w6: v1(1373.7,603.56) 1373.79,603.51 U1.38@1373.79,557.1
  Mid Layer w6: v1(768.15,232.87) 1085.19,232.87 1258.54,406.22 1315.69,406.22 1373.7,464.23 v1(1373.7,603.56)
  Bottom Signal Layer w6: C38.1@741.28,465.44 741.28,396.97 759.48,378.77 759.48,350.71 R35.1@741.28,332.5 741.28,326.84 768.15,299.97 v1(768.15,232.87)
MCU_A10/B1/C10: C39.1 R36.1 U1.40 | length 1430.1
  Top Signal Layer w6: v1(522.24,257.14) 522.24,291.68 558.42,327.86 C39.1@558.42,465.5 ; v1(1413.08,603.77) 1413.16,603.69 U1.40@1413.16,557.1
  Mid Layer w6: v1(522.24,257.14) 638.75,257.14 693.52,202.37 783.29,202.37 790.01,209.09 1100.52,209.09 1268.59,377.16 1323.57,377.16 1413.08,466.67 v1(1413.08,603.77)
MCU_A11/B10/C0/PGA2_OUT: C40.1 C97.2 R37.1 U1.20 | length 791.3
  Top Signal Layer w6: R37.1@612.88,332.57 C40.1@612.88,465.5 612.88,468.37 v1(652.3,507.79) ; v1(1011.48,725.35) 1009.01,725.35 1015.84,718.52 U1.20@1074.57,718.52
  Mid Layer w6: v1(652.3,507.79) 743.58,507.79 752.35,516.56 822.26,516.56 1011.48,705.78 v1(1011.48,725.35) v1@1009.57,725.35
  Bottom Signal Layer w6: C97.2@977.93,777.72 1011.48,744.17 v1(1011.48,725.35)
MCU_A12/C5: C41.1 R38.1 U1.28 | length 658.9
  Top Signal Layer w6: R38.1@815.27,332.5 805.33,342.45 v1(805.33,371.51) 805.33,455.49 C41.1@815.34,465.5 ; U1.28@1176.94,557.1 v1(1176.92,605.99)
  Mid Layer w6: v1(805.33,371.51) 823.03,389.21 960.14,389.21 v1(1176.92,605.99)
MCU_A14/B14/C4/PGA1_OUT: C42.1 C96.2 R39.1 U1.19 | length 703.9
  Top Signal Layer w6: v1(1024.66,764.34) 1024.66,752.97 1039.43,738.2 U1.19@1074.57,738.2
  Mid Layer w6: v1(778.86,492.55) 813.81,492.55 1029.32,708.07 1029.32,759.68 v1(1024.66,764.34)
  Bottom Signal Layer w6: v1(778.86,492.55) 788.29,492.55 C42.1@815.34,465.5 825.01,455.83 825.01,348.05 815.27,338.31 R39.1@815.27,332.5 ; v1(1024.66,764.34) 1067.56,764.34 C96.2@1072.44,759.46
MCU_B0/C11: C44.1 R41.1 U1.41 | length 1273.6
  Top Signal Layer w6: v1(643.93,210.83) 657.95,224.85 657.95,298.57 686.81,327.43 R41.1@686.81,332.5 ; R41.1@686.88,332.57 C44.1@686.88,465.5 ; v1(1432.84,507.64) U1.41@1432.84,557.1
  Mid Layer w6: v1(643.93,210.83) 663.39,191.37 790.12,191.37 795.93,197.18 1108.11,197.18 1274.77,363.84 1329.72,363.84 1432.84,466.96 v1(1432.84,507.64)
